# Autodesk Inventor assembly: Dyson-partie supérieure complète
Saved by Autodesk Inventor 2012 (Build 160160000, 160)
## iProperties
Created: 2012-11
Part Number: Dyson-partie supérieure complète
Document SubType Name: Assembly
Designer: Administrateur
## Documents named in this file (3)
- F:\Dyson\SI\2_Présentation éleve\SW_AM01 complet\Composants importés\Dyson Air Multiplier-Assemblage final\Dyson-partie supérieure complète.iam
- F:\Dyson\SI\2_Présentation éleve\SW_AM01 complet\Composants importés\Dyson Air Multiplier-Assemblage final\Dyson-Partie supérieure 1.ipt
- F:\Dyson\SI\2_Présentation éleve\SW_AM01 complet\Composants importés\Dyson Air Multiplier-Assemblage final\Dyson-Partie supérieure 2.ipt
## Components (2 placed, 2 different names)
1. Dyson-Partie supérieure 1:1
2. Dyson-Partie supérieure 2:1
